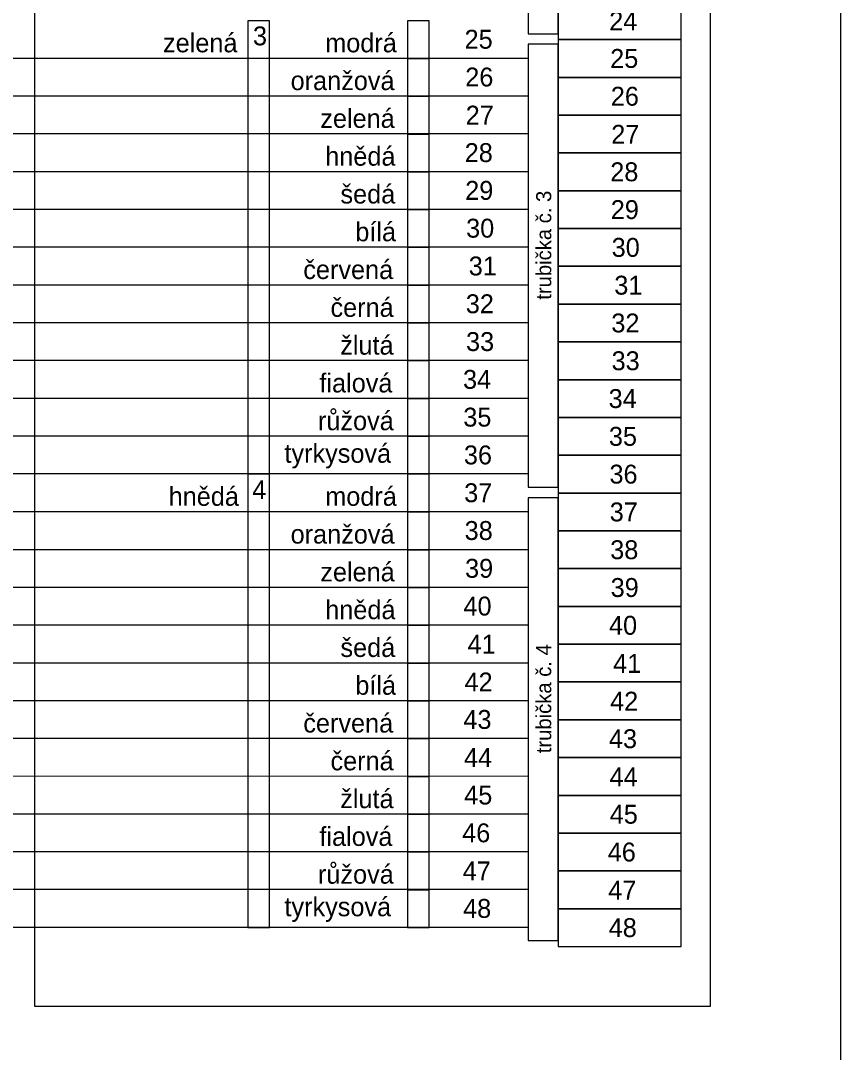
# Model space of a CAD drawing. Extents: x 1901 to 2519, y -3585 to -3154.
# Drawn here: x 2439.8 to 2516.2, y -3383.6 to -3287.5 of the extents above; entities that cross this region are included whole.
import ezdxf

# ---------------------------------------------------------------- set-up
doc = ezdxf.new("R2010")
doc.units = 0
doc.layers.add('rozvláknění', color=7, linetype='Continuous')
doc.layers.add('Vrstva 4', color=7, linetype='Continuous')

msp = doc.modelspace()

# ---------------------------------------------------------------- linework, layer by layer
at = {"layer": 'rozvláknění'}
for p, q in [((2489.935, -3287.484), (2489.918, -3287.484)), ((2487.131, -3291.004), (2392.43, -3291.005)), ((2489.935, -3291.004), (2489.918, -3291.004)), ((2487.131, -3294.522), (2392.43, -3294.523)), ((2489.935, -3294.524), (2489.918, -3294.524)), ((2487.131, -3298.04), (2392.43, -3298.041)), ((2487.131, -3298.044), (2487.131, -3301.564)), ((2489.935, -3298.044), (2489.918, -3298.044)), ((2487.131, -3301.558), (2392.43, -3301.559)), ((2489.935, -3301.564), (2489.918, -3301.564)), ((2487.131, -3305.076), (2392.43, -3305.078)), ((2489.935, -3305.084), (2489.918, -3305.084)), ((2487.131, -3308.595), (2392.43, -3308.596)), ((2487.131, -3308.604), (2487.131, -3312.124)), ((2489.935, -3308.604), (2489.918, -3308.604)), ((2487.131, -3312.113), (2392.43, -3312.114)), ((2489.935, -3312.124), (2489.918, -3312.124)), ((2487.131, -3315.631), (2392.43, -3315.632)), ((2489.935, -3315.644), (2489.918, -3315.644)), ((2487.131, -3319.149), (2392.43, -3319.15)), ((2487.131, -3319.164), (2487.131, -3322.684)), ((2489.935, -3319.164), (2489.918, -3319.164)), ((2487.131, -3322.667), (2392.43, -3322.669)), ((2489.935, -3322.684), (2489.918, -3322.684)), ((2487.131, -3326.186), (2392.43, -3326.187)), ((2489.935, -3326.204), (2489.918, -3326.204)), ((2487.131, -3329.704), (2392.43, -3329.705)), ((2489.935, -3329.724), (2489.918, -3329.724)), ((2487.131, -3333.244), (2392.43, -3333.245)), ((2489.935, -3333.244), (2489.918, -3333.244)), ((2487.131, -3336.762), (2392.43, -3336.763)), ((2489.935, -3336.764), (2489.918, -3336.764)), ((2487.131, -3340.28), (2392.43, -3340.281)), ((2487.131, -3340.284), (2487.131, -3343.804)), ((2489.935, -3340.284), (2489.918, -3340.284)), ((2487.131, -3343.798), (2392.43, -3343.799)), ((2489.935, -3343.804), (2489.918, -3343.804)), ((2487.131, -3347.316), (2392.43, -3347.318)), ((2489.935, -3347.324), (2489.918, -3347.324)), ((2487.131, -3350.835), (2392.43, -3350.836)), ((2487.131, -3350.844), (2487.131, -3354.364)), ((2489.935, -3350.844), (2489.918, -3350.844)), ((2487.131, -3354.353), (2392.43, -3354.354)), ((2489.935, -3354.364), (2489.918, -3354.364)), ((2487.131, -3357.871), (2392.43, -3357.872)), ((2489.935, -3357.884), (2489.918, -3357.884)), ((2487.131, -3361.389), (2392.43, -3361.39)), ((2487.131, -3361.404), (2487.131, -3364.924)), ((2489.935, -3361.404), (2489.918, -3361.404)), ((2487.131, -3364.907), (2392.43, -3364.909)), ((2489.935, -3364.924), (2489.918, -3364.924)), ((2487.131, -3368.426), (2392.43, -3368.427)), ((2489.935, -3368.444), (2489.918, -3368.444)), ((2487.131, -3371.944), (2392.43, -3371.945)), ((2489.935, -3371.964), (2489.918, -3371.964))]:
    msp.add_line(p, q, dxfattribs=at)
for points in [[(2504.11, -3178.544), (2441.124, -3178.543), (2441.124, -3379.277), (2504.11, -3379.277)], [(2489.918, -3247.438), (2487.131, -3247.438), (2487.131, -3288.698), (2489.918, -3288.698)], [(2501.378, -3285.724), (2489.935, -3285.724), (2489.935, -3289.244), (2501.378, -3289.244)], [(2461, -3329.706), (2463.041, -3329.706), (2463.041, -3287.487), (2461, -3287.487)], [(2477.919, -3287.487), (2475.878, -3287.487), (2475.878, -3291.006), (2477.919, -3291.006)], [(2501.378, -3289.244), (2489.935, -3289.244), (2489.935, -3292.764), (2501.378, -3292.764)], [(2489.918, -3289.678), (2487.131, -3289.678), (2487.131, -3330.938), (2489.918, -3330.938)], [(2477.919, -3291.006), (2475.878, -3291.006), (2475.878, -3294.524), (2477.919, -3294.524)], [(2501.378, -3292.764), (2489.935, -3292.764), (2489.935, -3296.284), (2501.378, -3296.284)], [(2477.919, -3294.524), (2475.878, -3294.524), (2475.878, -3298.042), (2477.919, -3298.042)], [(2501.378, -3296.284), (2489.935, -3296.284), (2489.935, -3299.804), (2501.378, -3299.804)], [(2477.919, -3298.042), (2475.878, -3298.042), (2475.878, -3301.56), (2477.919, -3301.56)], [(2501.378, -3299.804), (2489.935, -3299.804), (2489.935, -3303.324), (2501.378, -3303.324)], [(2477.919, -3301.56), (2475.878, -3301.56), (2475.878, -3305.078), (2477.919, -3305.078)], [(2501.378, -3303.324), (2489.935, -3303.324), (2489.935, -3306.844), (2501.378, -3306.844)], [(2477.919, -3305.078), (2475.878, -3305.078), (2475.878, -3308.597), (2477.919, -3308.597)], [(2501.378, -3306.844), (2489.935, -3306.844), (2489.935, -3310.364), (2501.378, -3310.364)], [(2477.919, -3308.597), (2475.878, -3308.597), (2475.878, -3312.115), (2477.919, -3312.115)], [(2501.378, -3310.364), (2489.935, -3310.364), (2489.935, -3313.884), (2501.378, -3313.884)], [(2477.919, -3312.115), (2475.878, -3312.115), (2475.878, -3315.633), (2477.919, -3315.633)], [(2501.378, -3313.884), (2489.935, -3313.884), (2489.935, -3317.404), (2501.378, -3317.404)], [(2477.919, -3315.633), (2475.878, -3315.633), (2475.878, -3319.151), (2477.919, -3319.151)], [(2501.378, -3317.404), (2489.935, -3317.404), (2489.935, -3320.924), (2501.378, -3320.924)], [(2477.919, -3319.151), (2475.878, -3319.151), (2475.878, -3322.669), (2477.919, -3322.669)], [(2501.378, -3320.924), (2489.935, -3320.924), (2489.935, -3324.444), (2501.378, -3324.444)], [(2477.919, -3322.669), (2475.878, -3322.669), (2475.878, -3326.188), (2477.919, -3326.188)], [(2501.378, -3324.444), (2489.935, -3324.444), (2489.935, -3327.964), (2501.378, -3327.964)], [(2477.919, -3326.188), (2475.878, -3326.188), (2475.878, -3329.706), (2477.919, -3329.706)], [(2501.378, -3327.964), (2489.935, -3327.964), (2489.935, -3331.484), (2501.378, -3331.484)], [(2461, -3371.946), (2463.041, -3371.946), (2463.041, -3329.727), (2461, -3329.727)], [(2477.919, -3329.727), (2475.878, -3329.727), (2475.878, -3333.246), (2477.919, -3333.246)], [(2501.378, -3331.484), (2489.935, -3331.484), (2489.935, -3335.004), (2501.378, -3335.004)], [(2489.918, -3331.918), (2487.131, -3331.918), (2487.131, -3373.178), (2489.918, -3373.178)], [(2477.919, -3333.246), (2475.878, -3333.246), (2475.878, -3336.764), (2477.919, -3336.764)], [(2501.378, -3335.004), (2489.935, -3335.004), (2489.935, -3338.524), (2501.378, -3338.524)], [(2477.919, -3336.764), (2475.878, -3336.764), (2475.878, -3340.282), (2477.919, -3340.282)], [(2501.378, -3338.524), (2489.935, -3338.524), (2489.935, -3342.044), (2501.378, -3342.044)], [(2477.919, -3340.282), (2475.878, -3340.282), (2475.878, -3343.8), (2477.919, -3343.8)], [(2501.378, -3342.044), (2489.935, -3342.044), (2489.935, -3345.564), (2501.378, -3345.564)], [(2477.919, -3343.8), (2475.878, -3343.8), (2475.878, -3347.318), (2477.919, -3347.318)], [(2501.378, -3345.564), (2489.935, -3345.564), (2489.935, -3349.084), (2501.378, -3349.084)], [(2477.919, -3347.318), (2475.878, -3347.318), (2475.878, -3350.837), (2477.919, -3350.837)], [(2501.378, -3349.084), (2489.935, -3349.084), (2489.935, -3352.604), (2501.378, -3352.604)], [(2477.919, -3350.837), (2475.878, -3350.837), (2475.878, -3354.355), (2477.919, -3354.355)], [(2501.378, -3352.604), (2489.935, -3352.604), (2489.935, -3356.124), (2501.378, -3356.124)], [(2477.919, -3354.355), (2475.878, -3354.355), (2475.878, -3357.873), (2477.919, -3357.873)], [(2501.378, -3356.124), (2489.935, -3356.124), (2489.935, -3359.644), (2501.378, -3359.644)], [(2477.919, -3357.873), (2475.878, -3357.873), (2475.878, -3361.391), (2477.919, -3361.391)], [(2501.378, -3359.644), (2489.935, -3359.644), (2489.935, -3363.164), (2501.378, -3363.164)], [(2477.919, -3361.391), (2475.878, -3361.391), (2475.878, -3364.909), (2477.919, -3364.909)], [(2501.378, -3363.164), (2489.935, -3363.164), (2489.935, -3366.684), (2501.378, -3366.684)], [(2477.919, -3364.909), (2475.878, -3364.909), (2475.878, -3368.428), (2477.919, -3368.428)], [(2501.378, -3366.684), (2489.935, -3366.684), (2489.935, -3370.204), (2501.378, -3370.204)], [(2477.919, -3368.428), (2475.878, -3368.428), (2475.878, -3371.946), (2477.919, -3371.946)], [(2501.378, -3370.204), (2489.935, -3370.204), (2489.935, -3373.724), (2501.378, -3373.724)]]:
    msp.add_lwpolyline(points, close=True, dxfattribs=at)
for points in [[(2461, -3329.706), (2463.041, -3329.706), (2463.041, -3287.487), (2461, -3287.487), (2461, -3329.706)], [(2477.919, -3287.487), (2475.878, -3287.487), (2475.878, -3291.006), (2477.919, -3291.006), (2477.919, -3287.487)], [(2477.919, -3291.006), (2475.878, -3291.006), (2475.878, -3294.524), (2477.919, -3294.524), (2477.919, -3291.006)], [(2477.919, -3294.524), (2475.878, -3294.524), (2475.878, -3298.042), (2477.919, -3298.042), (2477.919, -3294.524)], [(2477.919, -3298.042), (2475.878, -3298.042), (2475.878, -3301.56), (2477.919, -3301.56), (2477.919, -3298.042)], [(2477.919, -3301.56), (2475.878, -3301.56), (2475.878, -3305.078), (2477.919, -3305.078), (2477.919, -3301.56)], [(2477.919, -3305.078), (2475.878, -3305.078), (2475.878, -3308.597), (2477.919, -3308.597), (2477.919, -3305.078)], [(2477.919, -3308.597), (2475.878, -3308.597), (2475.878, -3312.115), (2477.919, -3312.115), (2477.919, -3308.597)], [(2477.919, -3312.115), (2475.878, -3312.115), (2475.878, -3315.633), (2477.919, -3315.633), (2477.919, -3312.115)], [(2477.919, -3315.633), (2475.878, -3315.633), (2475.878, -3319.151), (2477.919, -3319.151), (2477.919, -3315.633)], [(2477.919, -3319.151), (2475.878, -3319.151), (2475.878, -3322.669), (2477.919, -3322.669), (2477.919, -3319.151)], [(2477.919, -3322.669), (2475.878, -3322.669), (2475.878, -3326.188), (2477.919, -3326.188), (2477.919, -3322.669)], [(2477.919, -3326.188), (2475.878, -3326.188), (2475.878, -3329.706), (2477.919, -3329.706), (2477.919, -3326.188)], [(2461, -3371.946), (2463.041, -3371.946), (2463.041, -3329.727), (2461, -3329.727), (2461, -3371.946)], [(2477.919, -3329.727), (2475.878, -3329.727), (2475.878, -3333.246), (2477.919, -3333.246), (2477.919, -3329.727)], [(2477.919, -3333.246), (2475.878, -3333.246), (2475.878, -3336.764), (2477.919, -3336.764), (2477.919, -3333.246)], [(2477.919, -3336.764), (2475.878, -3336.764), (2475.878, -3340.282), (2477.919, -3340.282), (2477.919, -3336.764)], [(2477.919, -3340.282), (2475.878, -3340.282), (2475.878, -3343.8), (2477.919, -3343.8), (2477.919, -3340.282)], [(2477.919, -3343.8), (2475.878, -3343.8), (2475.878, -3347.318), (2477.919, -3347.318), (2477.919, -3343.8)], [(2477.919, -3347.318), (2475.878, -3347.318), (2475.878, -3350.837), (2477.919, -3350.837), (2477.919, -3347.318)], [(2477.919, -3350.837), (2475.878, -3350.837), (2475.878, -3354.355), (2477.919, -3354.355), (2477.919, -3350.837)], [(2477.919, -3354.355), (2475.878, -3354.355), (2475.878, -3357.873), (2477.919, -3357.873), (2477.919, -3354.355)], [(2477.919, -3357.873), (2475.878, -3357.873), (2475.878, -3361.391), (2477.919, -3361.391), (2477.919, -3357.873)], [(2477.919, -3361.391), (2475.878, -3361.391), (2475.878, -3364.909), (2477.919, -3364.909), (2477.919, -3361.391)], [(2477.919, -3364.909), (2475.878, -3364.909), (2475.878, -3368.428), (2477.919, -3368.428), (2477.919, -3364.909)], [(2477.919, -3368.428), (2475.878, -3368.428), (2475.878, -3371.946), (2477.919, -3371.946), (2477.919, -3368.428)]]:
    msp.add_lwpolyline(points, dxfattribs=at)
at = {"layer": 'Vrstva 4'}
msp.add_lwpolyline([(1901.224, -3154.468), (2516.224, -3154.468), (2516.224, -3584.968), (1901.224, -3584.968)], close=True, dxfattribs=at)

# ---------------------------------------------------------------- texts
at = {"layer": 'rozvláknění'}
for s, p in [('24', (2494.684, -3288.392)), ('zelená', (2453.111, -3290.432)), ('3', (2461.49, -3289.783)), ('modrá', (2468.222, -3290.432)), ('25', (2481.209, -3290.094)), ('25', (2494.773, -3291.883)), ('oranžová', (2464.996, -3293.952)), ('26', (2481.27, -3293.614)), ('26', (2494.833, -3295.403)), ('zelená', (2467.766, -3297.472)), ('27', (2481.312, -3297.164)), ('27', (2494.875, -3298.952)), ('hnědá', (2468.224, -3300.992)), ('28', (2481.22, -3300.654)), ('28', (2494.784, -3302.443)), ('šedá', (2469.641, -3304.512)), ('29', (2481.267, -3304.174)), ('29', (2494.83, -3305.963)), ('bílá', (2471.029, -3308.032)), ('30', (2481.351, -3307.694)), ('30', (2494.914, -3309.483)), ('červená', (2466.181, -3311.552)), ('31', (2481.596, -3311.214)), ('31', (2495.159, -3313.003)), ('černá', (2468.713, -3315.072)), ('32', (2481.321, -3314.734)), ('32', (2494.884, -3316.523)), ('žlutá', (2469.621, -3318.592)), ('33', (2481.344, -3318.254)), ('33', (2494.907, -3320.043)), ('fialová', (2467.683, -3322.112)), ('34', (2481.064, -3321.774)), ('34', (2494.627, -3323.563)), ('růžová', (2467.546, -3325.632)), ('35', (2481.089, -3325.294)), ('35', (2494.653, -3327.083)), ('tyrkysová', (2464.422, -3328.664)), ('36', (2481.145, -3328.814)), ('36', (2494.708, -3330.603)), ('hnědá', (2453.634, -3332.672)), ('4', (2461.426, -3332.053)), ('modrá', (2468.222, -3332.672)), ('37', (2481.169, -3332.334)), ('37', (2494.733, -3334.123)), ('oranžová', (2464.996, -3336.192)), ('38', (2481.213, -3335.854)), ('38', (2494.777, -3337.643)), ('zelená', (2467.766, -3339.712)), ('39', (2481.255, -3339.374)), ('39', (2494.819, -3341.163)), ('hnědá', (2468.224, -3343.232)), ('40', (2481.104, -3342.894)), ('40', (2494.667, -3344.683)), ('šedá', (2469.641, -3346.752)), ('41', (2481.484, -3346.444)), ('41', (2495.048, -3348.232)), ('bílá', (2471.029, -3350.272)), ('42', (2481.204, -3349.964)), ('42', (2494.768, -3351.752)), ('červená', (2466.181, -3353.792)), ('43', (2481.097, -3353.454)), ('43', (2494.66, -3355.243)), ('černá', (2468.713, -3357.312)), ('44', (2481.152, -3357.004)), ('44', (2494.715, -3358.792)), ('žlutá', (2469.621, -3360.832)), ('45', (2481.172, -3360.494)), ('45', (2494.736, -3362.283)), ('fialová', (2467.683, -3364.352)), ('46', (2480.983, -3364.014)), ('46', (2494.547, -3365.803)), ('růžová', (2467.546, -3367.872)), ('47', (2481.03, -3367.564)), ('47', (2494.594, -3369.352)), ('tyrkysová', (2464.422, -3370.904)), ('48', (2481.07, -3371.054)), ('48', (2494.633, -3372.843))]:
    msp.add_text(s, height=1.76, dxfattribs=at).set_placement(p)
for s, p in [('trubička č. 3', (2489.286, -3313.476)), ('trubička č. 4', (2489.281, -3355.716))]:
    msp.add_text(s, height=1.408, rotation=90, dxfattribs=at).set_placement(p)

doc.saveas('drawing.dxf')
